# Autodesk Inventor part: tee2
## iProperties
Shininess: 64.0
Length Units: 11269
Angle Units: 11279
Time Units: 11290
Mass Units: 11283
Length Display Precision: 3
Angle Display Precision: 2
Compacted: True
Part Number: tee2
Document SubType Name: Modeling
Created: 2003-07
Designer: JB
Density: 0.0
Volumn: 0.0
Area: 0.0
PropertySet Name: Model Information
Control State: 0
Master: False
Checked Out: False
Author: JB
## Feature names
1. Extrusion1
2. Extrusion2
3. Extrusion3
4. Extrusion5
